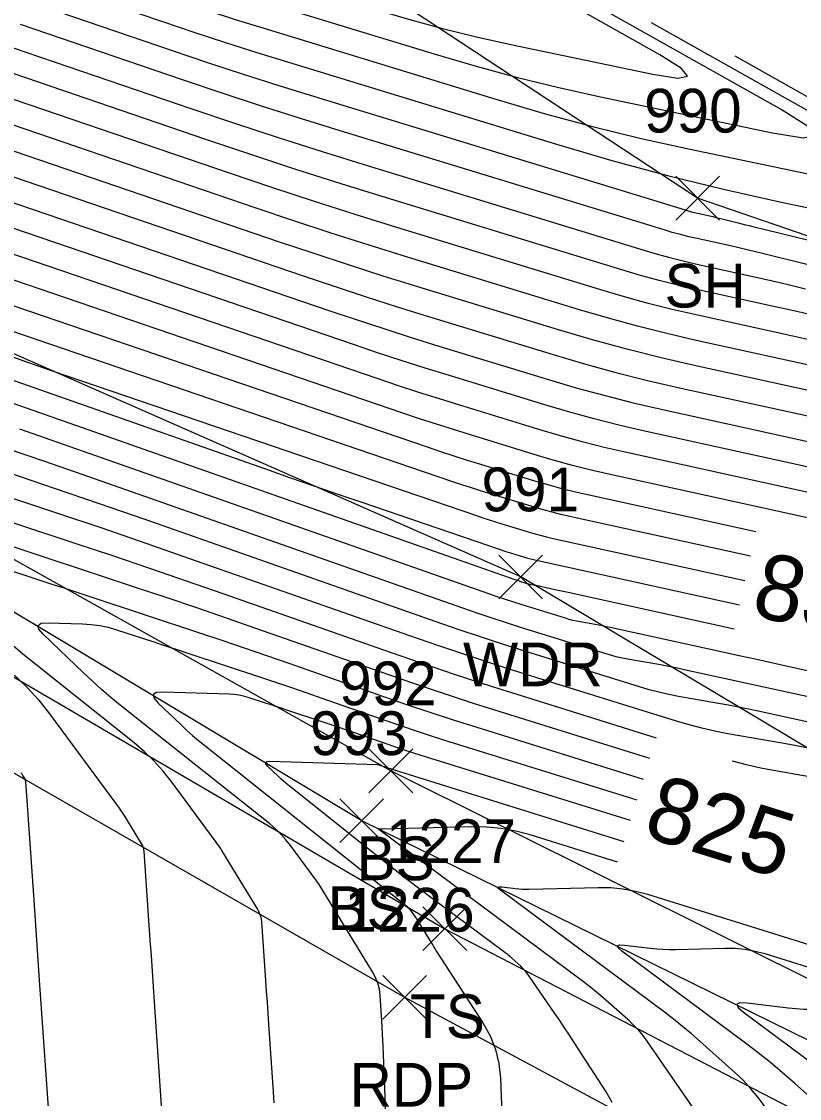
# Model space of a CAD drawing. Extents: x 1650836 to 1652450, y 332578 to 333908.
# Drawn here: x 1651914.59 to 1651950.15, y 332895.25 to 332944.49 of the extents above; entities that cross this region are included whole.
import ezdxf

# ---------------------------------------------------------------- set-up
doc = ezdxf.new("R2010")
doc.units = 0
for name, color, linetype in [('L_A', 7, 'Continuous'), ('L_I', 7, 'Continuous'), ('L_TIC', 7, 'Continuous'), ('LAWA', 7, 'Continuous'), ('LELB', 7, 'Continuous'), ('LSOGCMA', 7, 'Continuous'), ('LSOGCMA_T', 7, 'Continuous'), ('LSOGCMI', 7, 'Continuous'), ('LSOGP', 7, 'Continuous'), ('P_A', 7, 'Continuous'), ('P_I', 7, 'Continuous'), ('P_TIC', 7, 'Continuous'), ('PET', 7, 'Continuous')]:
    doc.layers.add(name, color=color, linetype=linetype)

msp = doc.modelspace()

# ---------------------------------------------------------------- linework, layer by layer
at = {"layer": 'L_TIC'}
for points in [[(1651944.495, 332935.417), (1651946.495, 332937.417)], [(1651946.495, 332935.417), (1651944.495, 332937.417)], [(1651936.407, 332918.099), (1651938.407, 332920.099)], [(1651938.407, 332918.099), (1651936.407, 332920.099)], [(1651930.469, 332909.231), (1651932.469, 332911.231)], [(1651932.469, 332909.231), (1651930.469, 332911.231)], [(1651929.139, 332906.952), (1651931.139, 332908.952)], [(1651931.139, 332906.952), (1651929.139, 332908.952)], [(1651932.94, 332902.012), (1651934.94, 332904.012)], [(1651934.94, 332902.012), (1651932.94, 332904.012)]]:
    msp.add_lwpolyline(points, dxfattribs=at)
at = {"layer": 'LAWA'}
msp.add_lwpolyline([(1652029.035, 332873.993), (1652029.332, 332877.691), (1652041.456, 332881.438), (1652043.799, 332892.048), (1652028.411, 332887.059), (1652010.628, 332879.467), (1652005.763, 332881.337), (1651975.403, 332896.414), (1651937.407, 332919.099), (1651902.904, 332934.281), (1651873.829, 332953.989)], dxfattribs=at)
at = {"layer": 'LELB'}
for points in [[(1652004.611, 332876.377), (1652000.575, 332878.245), (1651971.943, 332890.057), (1651931.469, 332910.231), (1651899.444, 332928.179), (1651868.914, 332946.877)], [(1652004.611, 332876.377), (1652004.078, 332874.687), (1651998.585, 332874.498), (1651971.102, 332887.818), (1651930.139, 332907.952), (1651899.336, 332926.423), (1651867.782, 332944.676)], [(1651863.072, 332944.289), (1651896.914, 332924.632), (1651933.94, 332903.012), (1651966.422, 332886.181), (1652000.17, 332869.987)]]:
    msp.add_lwpolyline(points, dxfattribs=at)
at = {"layer": 'LSOGCMA'}
for points in [[(1651976.087, 332923.688), (1651965.103, 332926.363), (1651963.796, 332926.683), (1651962.491, 332927.004), (1651961.186, 332927.329), (1651959.881, 332927.655), (1651954.248, 332929.072), (1651953.151, 332929.343), (1651952.052, 332929.606), (1651950.952, 332929.861), (1651949.849, 332930.108), (1651945.435, 332931.078), (1651944.335, 332931.332), (1651943.24, 332931.608), (1651942.151, 332931.905), (1651941.068, 332932.225), (1651931.75, 332935.076), (1651929.839, 332935.669), (1651927.933, 332936.277), (1651926.032, 332936.9), (1651924.136, 332937.539), (1651911.612, 332941.814)], [(1651913.31, 332929.464), (1651914.649, 332928.995), (1651915.99, 332928.529), (1651917.332, 332928.067), (1651918.675, 332927.607), (1651935.391, 332921.901), (1651935.679, 332921.804), (1651935.968, 332921.709), (1651936.257, 332921.617), (1651936.547, 332921.527), (1651937.71, 332921.171), (1651938.002, 332921.085), (1651938.295, 332921.005), (1651938.589, 332920.931), (1651938.885, 332920.862), (1651947.661, 332918.933)], [(1651931.6, 332885.693), (1651931.125, 332897.63), (1651931.112, 332897.921), (1651931.097, 332898.213), (1651931.081, 332898.504), (1651931.062, 332898.795), (1651930.983, 332899.959), (1651930.947, 332900.245), (1651930.877, 332900.52), (1651930.775, 332900.785), (1651930.639, 332901.039), (1651928.192, 332905.03), (1651928.158, 332905.084), (1651928.123, 332905.138), (1651928.087, 332905.191), (1651928.049, 332905.243), (1651926.888, 332906.813), (1651926.674, 332907.084), (1651926.444, 332907.339), (1651926.197, 332907.579), (1651925.933, 332907.802), (1651919.098, 332913.239), (1651918.666, 332913.591), (1651918.242, 332913.953), (1651917.827, 332914.324), (1651917.421, 332914.706), (1651915.579, 332916.476), (1651915.379, 332916.715), (1651915.349, 332916.882), (1651915.489, 332916.977), (1651915.8, 332917.001), (1651917.38, 332916.955), (1651917.773, 332916.93), (1651918.161, 332916.876), (1651918.544, 332916.795), (1651918.922, 332916.686), (1651920.587, 332916.142), (1651920.989, 332916.01), (1651921.392, 332915.878), (1651921.794, 332915.746), (1651922.196, 332915.613), (1651925.552, 332914.503), (1651926.245, 332914.273), (1651926.937, 332914.039), (1651927.628, 332913.801), (1651928.317, 332913.561), (1651931.241, 332912.535), (1651931.958, 332912.286), (1651932.679, 332912.044), (1651933.401, 332911.809), (1651934.125, 332911.579), (1651942.716, 332908.902)]]:
    msp.add_lwpolyline(points, dxfattribs=at)
at = {"layer": 'LSOGCMI'}
for points in [[(1651901.234, 332954.166), (1651912.723, 332950.788), (1651913.608, 332950.523), (1651914.489, 332950.248), (1651915.368, 332949.964), (1651916.244, 332949.671), (1651919.741, 332948.477), (1651920.616, 332948.182), (1651921.493, 332947.894), (1651922.373, 332947.613), (1651923.256, 332947.34), (1651930.728, 332945.053), (1651932.273, 332944.6), (1651933.826, 332944.181), (1651935.389, 332943.798), (1651936.96, 332943.45), (1651943.441, 332942.091), (1651944.593, 332941.909), (1651945.032, 332941.995), (1651944.758, 332942.349), (1651943.772, 332942.971), (1651935.715, 332947.508)], [(1651913.802, 332949.299), (1651914.868, 332948.954), (1651915.931, 332948.598), (1651920.172, 332947.15), (1651921.234, 332946.792), (1651922.299, 332946.443), (1651923.366, 332946.102), (1651924.436, 332945.77), (1651933.501, 332942.997), (1651935.374, 332942.447), (1651937.259, 332941.939), (1651939.154, 332941.474), (1651941.061, 332941.052), (1651948.922, 332939.403), (1651950.319, 332939.182), (1651950.852, 332939.287), (1651950.52, 332939.716), (1651949.323, 332940.471), (1651939.55, 332945.975)], [(1651914.369, 332947.944), (1651915.617, 332947.525), (1651920.604, 332945.823), (1651921.852, 332945.402), (1651923.104, 332944.992), (1651924.359, 332944.591), (1651925.617, 332944.201), (1651936.274, 332940.94), (1651938.476, 332940.294), (1651940.691, 332939.697), (1651942.92, 332939.15), (1651945.161, 332938.654), (1651954.403, 332936.716), (1651956.046, 332936.456), (1651956.672, 332936.578), (1651956.282, 332937.083), (1651954.875, 332937.971), (1651943.385, 332944.441)], [(1651913.869, 332946.934), (1651915.304, 332946.452), (1651921.036, 332944.496), (1651922.471, 332944.012), (1651923.909, 332943.541), (1651925.352, 332943.08), (1651926.798, 332942.632), (1651939.046, 332938.884), (1651941.578, 332938.141), (1651944.124, 332937.455), (1651946.685, 332936.826), (1651949.261, 332936.256), (1651959.884, 332934.028), (1651961.772, 332933.73), (1651962.492, 332933.87), (1651962.043, 332934.451), (1651960.426, 332935.47), (1651947.22, 332942.908)], [(1651914.991, 332945.379), (1651921.468, 332943.169), (1651923.089, 332942.623), (1651924.715, 332942.089), (1651926.344, 332941.569), (1651927.978, 332941.062), (1651944.925, 332935.877), (1651945.064, 332935.836), (1651945.205, 332935.798), (1651945.346, 332935.762), (1651945.488, 332935.73), (1651946.056, 332935.605), (1651946.198, 332935.573), (1651946.34, 332935.54), (1651946.481, 332935.506), (1651946.623, 332935.471), (1651947.348, 332935.289), (1651947.517, 332935.247), (1651947.685, 332935.205), (1651947.853, 332935.163), (1651948.021, 332935.122), (1651951.139, 332934.363)], [(1651950.482, 332933.38), (1651948.529, 332933.871), (1651948.149, 332933.965), (1651947.768, 332934.056), (1651947.387, 332934.145), (1651947.004, 332934.23), (1651945.474, 332934.567), (1651945.093, 332934.655), (1651944.714, 332934.75), (1651944.336, 332934.853), (1651943.961, 332934.964), (1651929.159, 332939.493), (1651927.337, 332940.058), (1651925.52, 332940.638), (1651923.707, 332941.233), (1651921.9, 332941.842), (1651914.546, 332944.352)], [(1651913.568, 332943.506), (1651922.331, 332940.515), (1651924.326, 332939.843), (1651926.325, 332939.187), (1651928.33, 332938.547), (1651930.339, 332937.923), (1651942.996, 332934.051), (1651943.608, 332933.871), (1651944.222, 332933.703), (1651944.84, 332933.547), (1651945.461, 332933.404), (1651947.953, 332932.856), (1651948.575, 332932.717), (1651949.196, 332932.573), (1651949.816, 332932.424), (1651950.435, 332932.271)], [(1651976.352, 332924.774), (1651960.832, 332928.553), (1651959.811, 332928.803), (1651958.789, 332929.055), (1651957.768, 332929.308), (1651956.748, 332929.564), (1651952.341, 332930.671), (1651951.484, 332930.884), (1651950.624, 332931.09), (1651949.763, 332931.289), (1651948.901, 332931.482), (1651945.448, 332932.241), (1651944.588, 332932.44), (1651943.731, 332932.655), (1651942.879, 332932.888), (1651942.032, 332933.138), (1651931.27, 332936.431), (1651929.197, 332937.074), (1651927.13, 332937.734), (1651925.068, 332938.41), (1651923.011, 332939.103), (1651912.59, 332942.66)], [(1651975.823, 332922.603), (1651969.373, 332924.174), (1651967.782, 332924.562), (1651966.192, 332924.954), (1651964.603, 332925.349), (1651963.014, 332925.747), (1651956.154, 332927.472), (1651954.818, 332927.802), (1651953.48, 332928.123), (1651952.14, 332928.433), (1651950.797, 332928.734), (1651945.422, 332929.916), (1651944.082, 332930.225), (1651942.749, 332930.56), (1651941.423, 332930.923), (1651940.103, 332931.312), (1651932.229, 332933.721), (1651930.481, 332934.264), (1651928.737, 332934.82), (1651926.997, 332935.391), (1651925.262, 332935.975), (1651910.635, 332940.968)], [(1651975.559, 332921.517), (1651973.643, 332921.984), (1651971.768, 332922.442), (1651969.894, 332922.904), (1651968.02, 332923.37), (1651966.148, 332923.839), (1651958.06, 332925.872), (1651956.486, 332926.261), (1651954.908, 332926.639), (1651953.328, 332927.005), (1651951.746, 332927.359), (1651945.409, 332928.753), (1651943.829, 332929.117), (1651942.258, 332929.513), (1651940.694, 332929.94), (1651939.139, 332930.399), (1651932.709, 332932.366), (1651931.123, 332932.858), (1651929.54, 332933.363), (1651927.962, 332933.881), (1651926.387, 332934.411), (1651909.657, 332940.122)], [(1651908.679, 332939.276), (1651927.513, 332932.848), (1651928.926, 332932.371), (1651930.343, 332931.907), (1651931.764, 332931.453), (1651933.189, 332931.011), (1651938.895, 332929.265), (1651940.325, 332928.843), (1651941.763, 332928.451), (1651943.208, 332928.087), (1651944.661, 332927.752), (1651952.694, 332925.985), (1651954.517, 332925.577), (1651956.336, 332925.156), (1651958.153, 332924.721), (1651959.966, 332924.272), (1651970.155, 332921.71), (1651971.875, 332921.28), (1651973.595, 332920.853), (1651975.316, 332920.428), (1651977.037, 332920.008), (1651985.985, 332917.829), (1651986.678, 332917.66), (1651987.37, 332917.49)], [(1651907.701, 332938.43), (1651928.638, 332931.284), (1651929.891, 332930.862), (1651931.147, 332930.45), (1651932.406, 332930.048), (1651933.669, 332929.656), (1651938.725, 332928.109), (1651939.993, 332927.735), (1651941.267, 332927.387), (1651942.548, 332927.064), (1651943.836, 332926.768), (1651953.642, 332924.611)], [(1651954.591, 332923.237), (1651943.011, 332925.783), (1651941.888, 332926.042), (1651940.772, 332926.323), (1651939.661, 332926.627), (1651938.556, 332926.953), (1651934.148, 332928.301), (1651933.048, 332928.643), (1651931.95, 332928.993), (1651930.856, 332929.352), (1651929.764, 332929.72), (1651906.723, 332937.584)], [(1651955.539, 332921.863), (1651942.186, 332924.799), (1651941.228, 332925.02), (1651940.276, 332925.26), (1651939.329, 332925.518), (1651938.387, 332925.796), (1651934.628, 332926.946), (1651933.69, 332927.237), (1651932.754, 332927.536), (1651931.82, 332927.842), (1651930.889, 332928.156), (1651905.745, 332936.739)], [(1651987.01, 332912.964), (1651986.448, 332913.106), (1651985.886, 332913.251), (1651983.64, 332913.83), (1651983.079, 332913.975), (1651982.517, 332914.118), (1651981.955, 332914.261), (1651981.392, 332914.403), (1651967.173, 332917.978), (1651964.614, 332918.611), (1651962.05, 332919.225), (1651959.481, 332919.82), (1651956.908, 332920.396), (1651941.361, 332923.815), (1651940.569, 332923.997), (1651939.781, 332924.196), (1651938.997, 332924.41), (1651938.218, 332924.64), (1651935.108, 332925.591), (1651934.332, 332925.832), (1651933.557, 332926.079), (1651932.785, 332926.333), (1651932.014, 332926.592), (1651904.767, 332935.893)], [(1651948.15, 332921.156), (1651940.535, 332922.831), (1651939.909, 332922.975), (1651939.285, 332923.132), (1651938.665, 332923.302), (1651938.049, 332923.484), (1651935.588, 332924.236), (1651934.974, 332924.427), (1651934.361, 332924.623), (1651933.75, 332924.823), (1651933.14, 332925.028), (1651903.789, 332935.047)], [(1651947.906, 332920.044), (1651939.71, 332921.847), (1651939.249, 332921.953), (1651938.79, 332922.068), (1651938.333, 332922.193), (1651937.879, 332922.327), (1651936.068, 332922.881), (1651935.615, 332923.022), (1651935.164, 332923.166), (1651934.714, 332923.313), (1651934.265, 332923.465), (1651904.264, 332933.705)], [(1651908.844, 332929.968), (1651925.744, 332924.035), (1651926.845, 332923.65), (1651927.946, 332923.268), (1651929.048, 332922.887), (1651930.151, 332922.51), (1651936.516, 332920.337), (1651936.643, 332920.294), (1651936.771, 332920.252), (1651936.899, 332920.211), (1651937.027, 332920.172), (1651937.541, 332920.014), (1651937.67, 332919.976), (1651937.799, 332919.941), (1651937.929, 332919.908), (1651938.06, 332919.878), (1651947.417, 332917.821)], [(1651947.172, 332916.709), (1651939.573, 332918.38), (1651939.421, 332918.413), (1651939.269, 332918.447), (1651939.117, 332918.48), (1651938.965, 332918.513), (1651938.113, 332918.7), (1651938.084, 332918.706), (1651938.054, 332918.712), (1651938.025, 332918.718), (1651937.995, 332918.723), (1651937.876, 332918.744), (1651937.847, 332918.75), (1651937.817, 332918.756), (1651937.788, 332918.764), (1651937.76, 332918.772), (1651937.419, 332918.878), (1651937.353, 332918.899), (1651937.287, 332918.921), (1651937.221, 332918.943), (1651937.156, 332918.966), (1651911.68, 332927.909)], [(1651968.919, 332910.761), (1651949.959, 332914.93), (1651949.079, 332915.124), (1651948.199, 332915.317), (1651947.319, 332915.51), (1651946.439, 332915.703), (1651941.499, 332916.785), (1651941.328, 332916.822), (1651941.157, 332916.856), (1651940.986, 332916.889), (1651940.814, 332916.92), (1651940.127, 332917.041), (1651939.956, 332917.073), (1651939.786, 332917.112), (1651939.618, 332917.155), (1651939.45, 332917.205), (1651937.478, 332917.819), (1651937.095, 332917.941), (1651936.712, 332918.065), (1651936.331, 332918.194), (1651935.951, 332918.325), (1651914.516, 332925.85)], [(1651913.935, 332924.973), (1651915.645, 332924.386), (1651917.352, 332923.791), (1651934.746, 332917.685), (1651935.441, 332917.444), (1651936.138, 332917.21), (1651936.837, 332916.982), (1651937.538, 332916.76), (1651941.141, 332915.637), (1651941.447, 332915.547), (1651941.755, 332915.467), (1651942.065, 332915.397), (1651942.378, 332915.337), (1651943.634, 332915.117), (1651943.947, 332915.06), (1651944.26, 332915), (1651944.573, 332914.937), (1651944.884, 332914.87), (1651953.912, 332912.893)], [(1651964.201, 332909.466), (1651948.27, 332912.956), (1651947.817, 332913.052), (1651947.363, 332913.144), (1651946.909, 332913.231), (1651946.453, 332913.314), (1651944.628, 332913.634), (1651944.174, 332913.721), (1651943.723, 332913.823), (1651943.276, 332913.939), (1651942.832, 332914.069), (1651937.597, 332915.701), (1651936.578, 332916.023), (1651935.563, 332916.355), (1651934.551, 332916.695), (1651933.541, 332917.044), (1651920.188, 332921.732), (1651918.146, 332922.444), (1651916.101, 332923.146), (1651914.052, 332923.839)], [(1651908.829, 332923.355), (1651917.063, 332920.633), (1651918.75, 332920.071), (1651920.435, 332919.501), (1651922.116, 332918.924), (1651923.796, 332918.339), (1651931.131, 332915.763), (1651932.77, 332915.196), (1651934.414, 332914.644), (1651936.062, 332914.106), (1651937.715, 332913.583), (1651943.603, 332911.748)], [(1651950.467, 332911.288), (1651949.87, 332911.403), (1651949.272, 332911.511), (1651946.879, 332911.93), (1651946.283, 332912.045), (1651945.692, 332912.178), (1651945.105, 332912.33), (1651944.523, 332912.502), (1651937.656, 332914.642), (1651936.32, 332915.065), (1651934.988, 332915.499), (1651933.66, 332915.946), (1651932.336, 332916.404), (1651922.288, 332919.931), (1651920.279, 332920.631), (1651918.267, 332921.322), (1651916.252, 332922.004), (1651914.233, 332922.676)], [(1651943.308, 332910.799), (1651936.666, 332912.869), (1651935.249, 332913.318), (1651933.836, 332913.779), (1651932.427, 332914.252), (1651931.022, 332914.738), (1651925.303, 332916.746), (1651923.954, 332917.216), (1651922.602, 332917.68), (1651921.249, 332918.138), (1651919.893, 332918.59), (1651913.326, 332920.761)], [(1651912.308, 332919.974), (1651915.382, 332918.969), (1651915.977, 332918.774), (1651916.572, 332918.579), (1651917.167, 332918.383), (1651917.761, 332918.187), (1651922.723, 332916.547), (1651923.747, 332916.205), (1651924.77, 332915.859), (1651925.791, 332915.509), (1651926.81, 332915.154), (1651931.131, 332913.637), (1651932.193, 332913.269), (1651933.257, 332912.911), (1651934.325, 332912.563), (1651935.395, 332912.224), (1651943.012, 332909.85)], [(1651926.135, 332895.046), (1651926.101, 332895.557), (1651925.893, 332898.654), (1651925.86, 332899.152), (1651925.826, 332899.65), (1651925.793, 332900.148), (1651925.758, 332900.646), (1651925.576, 332903.305), (1651925.556, 332903.467), (1651925.516, 332903.623), (1651925.458, 332903.772), (1651925.381, 332903.916), (1651923.74, 332906.593), (1651923.68, 332906.689), (1651923.617, 332906.784), (1651923.553, 332906.878), (1651923.486, 332906.97), (1651921.426, 332909.756), (1651921.046, 332910.237), (1651920.637, 332910.69), (1651920.199, 332911.115), (1651919.731, 332911.512), (1651915.235, 332915.088), (1651914.652, 332915.563), (1651914.08, 332916.052)], [(1651914.267, 332914.603), (1651914.838, 332914.049), (1651915.371, 332913.458), (1651915.867, 332912.831), (1651918.923, 332908.697), (1651919.019, 332908.565), (1651919.111, 332908.43), (1651919.201, 332908.294), (1651919.288, 332908.156), (1651920.073, 332906.876), (1651920.113, 332906.8), (1651920.144, 332906.721), (1651920.165, 332906.639), (1651920.175, 332906.554), (1651920.458, 332902.488), (1651920.507, 332901.782), (1651920.556, 332901.075), (1651920.604, 332900.369), (1651920.652, 332899.662), (1651921.02, 332894.241)], [(1651942.421, 332907.953), (1651932.855, 332910.935), (1651932.477, 332911.054), (1651932.1, 332911.177), (1651931.724, 332911.303), (1651931.35, 332911.433), (1651929.825, 332911.968), (1651929.465, 332912.094), (1651929.105, 332912.218), (1651928.744, 332912.34), (1651928.382, 332912.46), (1651926.631, 332913.039), (1651926.421, 332913.108), (1651926.211, 332913.177), (1651926.002, 332913.246), (1651925.791, 332913.315), (1651924.951, 332913.59), (1651924.74, 332913.651), (1651924.526, 332913.696), (1651924.309, 332913.726), (1651924.089, 332913.74), (1651921.027, 332913.83), (1651920.742, 332913.807), (1651920.614, 332913.72), (1651920.641, 332913.567), (1651920.825, 332913.348), (1651921.87, 332912.343), (1651922.134, 332912.095), (1651922.404, 332911.854), (1651922.679, 332911.618), (1651922.96, 332911.389), (1651932.135, 332904.092), (1651932.195, 332904.042), (1651932.25, 332903.988), (1651932.302, 332903.93), (1651932.351, 332903.869), (1651932.612, 332903.515), (1651932.621, 332903.503), (1651932.629, 332903.492), (1651932.637, 332903.48), (1651932.645, 332903.467), (1651933.325, 332902.358), (1651933.384, 332902.262), (1651933.444, 332902.166), (1651933.505, 332902.07), (1651933.566, 332901.975), (1651935.684, 332898.704), (1651936.014, 332898.113), (1651936.257, 332897.495), (1651936.413, 332896.849), (1651936.482, 332896.176), (1651936.65, 332891.634)], [(1651941.589, 332895.062), (1651941.314, 332895.561), (1651939.854, 332897.815), (1651939.636, 332898.149), (1651939.416, 332898.481), (1651939.194, 332898.811), (1651938.969, 332899.14), (1651937.771, 332900.881), (1651937.69, 332900.992), (1651937.602, 332901.098), (1651937.508, 332901.198), (1651937.408, 332901.293), (1651936.996, 332901.663), (1651936.892, 332901.754), (1651936.786, 332901.843), (1651936.678, 332901.929), (1651936.568, 332902.013), (1651933.363, 332904.397), (1651932.794, 332904.824), (1651932.228, 332905.255), (1651931.666, 332905.692), (1651931.107, 332906.133), (1651926.823, 332909.54), (1651926.693, 332909.646), (1651926.566, 332909.754), (1651926.441, 332909.866), (1651926.319, 332909.981), (1651925.836, 332910.445), (1651925.751, 332910.546), (1651925.739, 332910.617), (1651925.798, 332910.657), (1651925.93, 332910.667), (1651930.855, 332910.523), (1651930.873, 332910.522), (1651930.891, 332910.52), (1651930.909, 332910.516), (1651930.926, 332910.511), (1651931.014, 332910.482), (1651931.066, 332910.465), (1651931.212, 332910.417), (1651931.242, 332910.407), (1651931.272, 332910.397), (1651931.302, 332910.386), (1651931.332, 332910.376), (1651931.459, 332910.331), (1651931.49, 332910.321), (1651931.521, 332910.31), (1651931.553, 332910.3), (1651931.584, 332910.29), (1651942.125, 332907.005)], [(1651947.08, 332910.684), (1651947.66, 332910.534), (1651948.392, 332910.369), (1651949.13, 332910.227), (1651952.092, 332909.707), (1651952.831, 332909.574), (1651953.57, 332909.432), (1651954.306, 332909.283), (1651955.041, 332909.126), (1651972.529, 332905.295), (1651973.746, 332905.02), (1651974.96, 332904.73), (1651976.171, 332904.425), (1651977.377, 332904.105), (1651982.196, 332902.792), (1651983.406, 332902.489), (1651984.624, 332902.233), (1651985.852, 332902.026), (1651987.088, 332901.868)], [(1651915.906, 332893.528), (1651915.416, 332900.654), (1651915.352, 332901.571), (1651915.289, 332902.488), (1651915.225, 332903.404), (1651915.16, 332904.321), (1651914.779, 332909.744), (1651914.774, 332909.781), (1651914.765, 332909.818), (1651914.751, 332909.852), (1651914.733, 332909.886), (1651914.653, 332910.016), (1651914.633, 332910.049), (1651914.612, 332910.081), (1651914.59, 332910.112), (1651914.567, 332910.143)], [(1651941.83, 332906.056), (1651937.845, 332907.298), (1651937.186, 332907.474), (1651936.519, 332907.595), (1651935.845, 332907.66), (1651935.163, 332907.67), (1651931.088, 332907.564), (1651931.069, 332907.563), (1651931.049, 332907.564), (1651931.029, 332907.565), (1651931.01, 332907.567), (1651930.932, 332907.577), (1651930.917, 332907.577), (1651930.911, 332907.574), (1651930.913, 332907.568), (1651930.925, 332907.558), (1651940.273, 332900.602), (1651940.539, 332900.4), (1651940.799, 332900.192), (1651941.055, 332899.979), (1651941.305, 332899.759), (1651942.299, 332898.869), (1651942.54, 332898.64), (1651942.767, 332898.397), (1651942.978, 332898.142), (1651943.174, 332897.874), (1651947.071, 332892.213)], [(1651948.578, 332894.867), (1651948.266, 332895.292), (1651947.931, 332895.697), (1651947.573, 332896.081), (1651947.191, 332896.444), (1651945.615, 332897.855), (1651945.218, 332898.203), (1651944.812, 332898.542), (1651944.4, 332898.872), (1651943.979, 332899.192), (1651936.482, 332904.77), (1651936.39, 332904.851), (1651936.37, 332904.903), (1651936.42, 332904.926), (1651936.542, 332904.921), (1651937.17, 332904.846), (1651937.327, 332904.83), (1651937.485, 332904.819), (1651937.642, 332904.815), (1651937.8, 332904.816), (1651940.951, 332904.899), (1651941.526, 332904.89), (1651942.094, 332904.835), (1651942.655, 332904.734), (1651943.21, 332904.585), (1651958.049, 332899.96)], [(1651952.265, 332893.855), (1651949.925, 332895.951), (1651949.381, 332896.428), (1651948.826, 332896.892), (1651948.261, 332897.343), (1651947.685, 332897.782), (1651942.038, 332901.983), (1651941.867, 332902.133), (1651941.829, 332902.231), (1651941.923, 332902.275), (1651942.151, 332902.266), (1651943.33, 332902.124), (1651943.625, 332902.094), (1651943.92, 332902.075), (1651944.216, 332902.067), (1651944.512, 332902.069), (1651946.739, 332902.127), (1651947.206, 332902.12), (1651947.668, 332902.076), (1651948.125, 332901.993), (1651948.576, 332901.872), (1651960.619, 332898.119)], [(1651967.541, 332895.22), (1651966.448, 332895.43), (1651965.363, 332895.674), (1651964.287, 332895.954), (1651963.219, 332896.268), (1651953.942, 332899.159), (1651953.594, 332899.252), (1651953.242, 332899.316), (1651952.886, 332899.35), (1651952.526, 332899.356), (1651951.078, 332899.318), (1651950.716, 332899.315), (1651950.355, 332899.325), (1651949.995, 332899.349), (1651949.635, 332899.385), (1651947.761, 332899.611), (1651947.427, 332899.624), (1651947.287, 332899.559), (1651947.344, 332899.416), (1651947.595, 332899.195), (1651951.391, 332896.371), (1651952.122, 332895.815), (1651952.839, 332895.242)]]:
    msp.add_lwpolyline(points, dxfattribs=at)
at = {"layer": 'LSOGP'}
msp.add_lwpolyline([(1651992.258, 332920.35), (1651945.495, 332936.417), (1651917.714, 332954.706), (1651888.541, 332971.502), (1651873.829, 332953.989), (1651868.914, 332946.877), (1651867.782, 332944.676), (1651863.072, 332944.289), (1651861.092, 332941.311), (1651856.451, 332944.302), (1651851.811, 332947.292), (1651847.171, 332950.282), (1651842.53, 332953.273), (1651837.89, 332956.263), (1651833.25, 332959.254), (1651828.61, 332962.244), (1651823.969, 332965.234), (1651818.103, 332969.162), (1651812.237, 332973.09)], dxfattribs=at)
at = {"layer": 'P_TIC'}
for points in [[(1651931.1, 332898.878), (1651933.1, 332900.878)], [(1651933.1, 332898.878), (1651931.1, 332900.878)]]:
    msp.add_lwpolyline(points, dxfattribs=at)
at = {"layer": 'PET'}
msp.add_lwpolyline([(1651782.185, 332994.087), (1651800.504, 332980.945), (1651823.969, 332965.234), (1651861.092, 332941.311), (1651895.497, 332920.881), (1651932.1, 332899.878), (1651964.344, 332882.546), (1651997.084, 332865.287), (1652030.302, 332847.665), (1652049.548, 332837.673), (1652081.974, 332820.953), (1652121.026, 332800.401), (1652157.819, 332781.161), (1652191.945, 332763.077), (1652232.596, 332742.33), (1652251.93, 332731.59), (1652295.202, 332708.727), (1652345.726, 332682.336), (1652379.152, 332664.868), (1652402.111, 332652.828)], dxfattribs=at)

# ---------------------------------------------------------------- texts
at = {"layer": 'L_A'}
for s, p in [('SH', (1651943.983, 332931.417)), ('WDR', (1651934.769, 332914.099)), ('BS', (1651929.91, 332905.231)), ('BS', (1651928.58, 332902.952)), ('TS', (1651932.35, 332898.012))]:
    msp.add_text(s, height=2, dxfattribs=at).set_placement(p)
at = {"layer": 'L_I'}
for s, p in [('990', (1651943.047, 332939.417)), ('991', (1651935.612, 332922.099)), ('992', (1651929.107, 332913.231)), ('993', (1651927.777, 332910.952)), ('1227', (1651931.248, 332906.012))]:
    msp.add_text(s, height=2, dxfattribs=at).set_placement(p)
at = {"layer": 'LSOGCMA_T'}
for s, rotation, p in [('830', 347.5978, (1651947.87, 332917.351)), ('825', 342.6898, (1651942.913, 332907.269))]:
    msp.add_text(s, height=3, rotation=rotation, dxfattribs=at).set_placement(p)
at = {"layer": 'P_A'}
msp.add_text('RDP', height=2, dxfattribs=at).set_placement((1651929.588, 332894.878))
at = {"layer": 'P_I'}
msp.add_text('1226', height=2, dxfattribs=at).set_placement((1651929.352, 332902.878))

doc.saveas('drawing.dxf')
